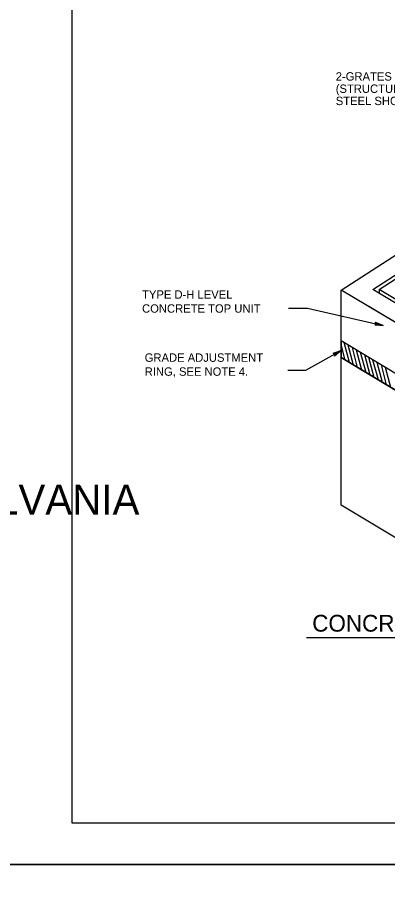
# Model space of a CAD drawing. Extents: x -6420 to 49575, y -4552 to 11624.
# Drawn here: x 4680 to 5115, y 9650 to 10669 of the extents above; entities that cross this region are included whole.
import ezdxf

# ---------------------------------------------------------------- set-up
doc = ezdxf.new("R2010")
doc.units = 0
doc.layers.add('1', color=7, linetype='Continuous')
doc.layers.add('PLT-BNDY', color=7, linetype='Continuous')

msp = doc.modelspace()

# ---------------------------------------------------------------- linework, layer by layer
at = {"layer": '1'}
for p, q in [((5060.3, 10349.3), (5525.6, 10649.5)), ((5217.8, 10254.8), (5060.3, 10349.3)), ((5060.3, 10289.7), (5060.3, 10349.3)), ((5105, 10350.1), (5105, 10345.5)), ((4998.4, 10328.2), (5021, 10328.2)), ((5021, 10328.2), (5109.6, 10307.7)), ((5217.8, 10254.8), (5092.9, 10329.8)), ((5060.3, 10270), (5060.3, 10289.7)), ((5018.7, 10255.4), (5060.3, 10278.2)), ((5217.8, 10175.5), (5060.3, 10270)), ((5060.3, 10096.8), (5060.3, 10270)), ((4997.9, 10255.4), (5018.7, 10255.4)), ((5217.8, 10002.3), (5060.3, 10096.8)), ((5019.8, 9941.8), (5692.6, 9941.8))]:
    msp.add_line(p, q, dxfattribs=at)
for points in [[(7323.1, 9724.3), (7323.1, 11574.7), (4744.3, 11574.7), (4744.3, 9724.3), (7323.1, 9724.3), (7323.1, 9810.8), (6666.9, 9810.8), (6666.9, 10023), (7323.1, 10023), (7323.1, 10118), (6666.9, 10118), (6666.9, 9724.3), (6925.4, 9724.3), (6925.4, 9810.8), (6925.4, 9724.3), (7178.1, 9724.3), (7178.1, 9810.8), (7178.1, 9770.4), (7323.1, 9770.4)], [(5217.3, 10282.7), (5105, 10350.1), (5313.6, 10484.7), (5426, 10417.3), (5217.3, 10282.7)], [(5217.4, 10278), (5097.6, 10349.9), (5218.7, 10428.1)], [(5109.6, 10307.7), (5099.7, 10308.1), (5100.1, 10308.3), (5100.5, 10308.4), (5100.8, 10308.7), (5101.1, 10309), (5101.2, 10309.3), (5101.3, 10309.6), (5101.3, 10309.9), (5101.4, 10310.3), (5101.2, 10310.6), (5101.1, 10311), (5100.8, 10311.3), (5100.5, 10311.7), (5109.6, 10307.7), (5100.8, 10311.3), (5101.1, 10311), (5109.6, 10307.7), (5101.2, 10310.6), (5101.4, 10310.3), (5109.6, 10307.7), (5101.3, 10309.9), (5101.3, 10309.6), (5109.6, 10307.7), (5101.2, 10309.3), (5101.1, 10309), (5109.6, 10307.7), (5100.8, 10308.7), (5100.5, 10308.4), (5109.6, 10307.7), (5100.1, 10308.3)], [(5065.2, 10267.1), (5060.3, 10285.3)], [(5070, 10264.2), (5063.7, 10287.6)], [(5074.9, 10261.3), (5068.6, 10284.7)], [(5079.7, 10258.4), (5073.5, 10281.8)], [(5060.3, 10278.2), (5052.6, 10271.9), (5052.8, 10272.3), (5053, 10272.7), (5053, 10273.1), (5053, 10273.4), (5052.9, 10273.8), (5052.8, 10274.1), (5052.6, 10274.3), (5052.4, 10274.6), (5052.1, 10274.8), (5051.7, 10275), (5051.3, 10275), (5050.8, 10275.1), (5060.3, 10278.2), (5051.3, 10275), (5051.7, 10275), (5060.3, 10278.2), (5052.1, 10274.8), (5052.4, 10274.6), (5060.3, 10278.2), (5052.6, 10274.3), (5052.8, 10274.1), (5060.3, 10278.2), (5052.9, 10273.8), (5053, 10273.4), (5060.3, 10278.2), (5053, 10273.1), (5053, 10272.7), (5060.3, 10278.2), (5052.8, 10272.3)], [(5084.6, 10255.4), (5078.3, 10278.9)], [(5089.5, 10252.5), (5083.2, 10276)], [(5094.3, 10249.6), (5088, 10273.1)], [(5099.2, 10246.7), (5092.9, 10270.2)], [(5104, 10243.8), (5097.7, 10267.2)], [(5108.9, 10240.9), (5102.6, 10264.3)], [(5113.7, 10238), (5107.5, 10261.4)], [(5118.6, 10235), (5112.3, 10258.5)]]:
    msp.add_lwpolyline(points, dxfattribs=at)
msp.add_lwpolyline([(5217.8, 10175.5), (5217.8, 10195.2), (5060.3, 10289.7), (5060.3, 10270)], close=True, dxfattribs=at)
at = {"layer": 'PLT-BNDY'}
for points in [[(4616.4, 11623.9), (7375.6, 11623.9), (7375.6, 9675.1), (4616.4, 9675.1)], [(4616.4, 9675.1), (7375.6, 9675.1), (7375.6, 7726.3), (4616.4, 7726.3)]]:
    msp.add_lwpolyline(points, close=True, dxfattribs=at)

# ---------------------------------------------------------------- texts
at = {"layer": '1'}
for s, height, p in [('2-GRATES', 9.84, (5054, 10595)), ('(STRUCTURAL', 9.843, (5054, 10580.6)), ('STEEL SHOWN)', 9.843, (5054, 10566.3)), ('TYPE D-H LEVEL', 9.843, (4826.7, 10339.1)), ('CONCRETE TOP UNIT', 9.843, (4826.7, 10322.7)), ('GRADE ADJUSTMENT', 9.843, (4829.8, 10265.1)), ('RING, SEE NOTE 4.', 9.843, (4829.8, 10248.7)), ('COMMONWEALTH OF PENNSYLVANIA', 35.379, (3950.9, 10085.7)), ('CONCRETE TOP UNIT - TYPE D-H LEVEL', 19.685, (5026.4, 9948.5))]:
    msp.add_text(s, height=height, dxfattribs=at).set_placement(p)

doc.saveas('drawing.dxf')
